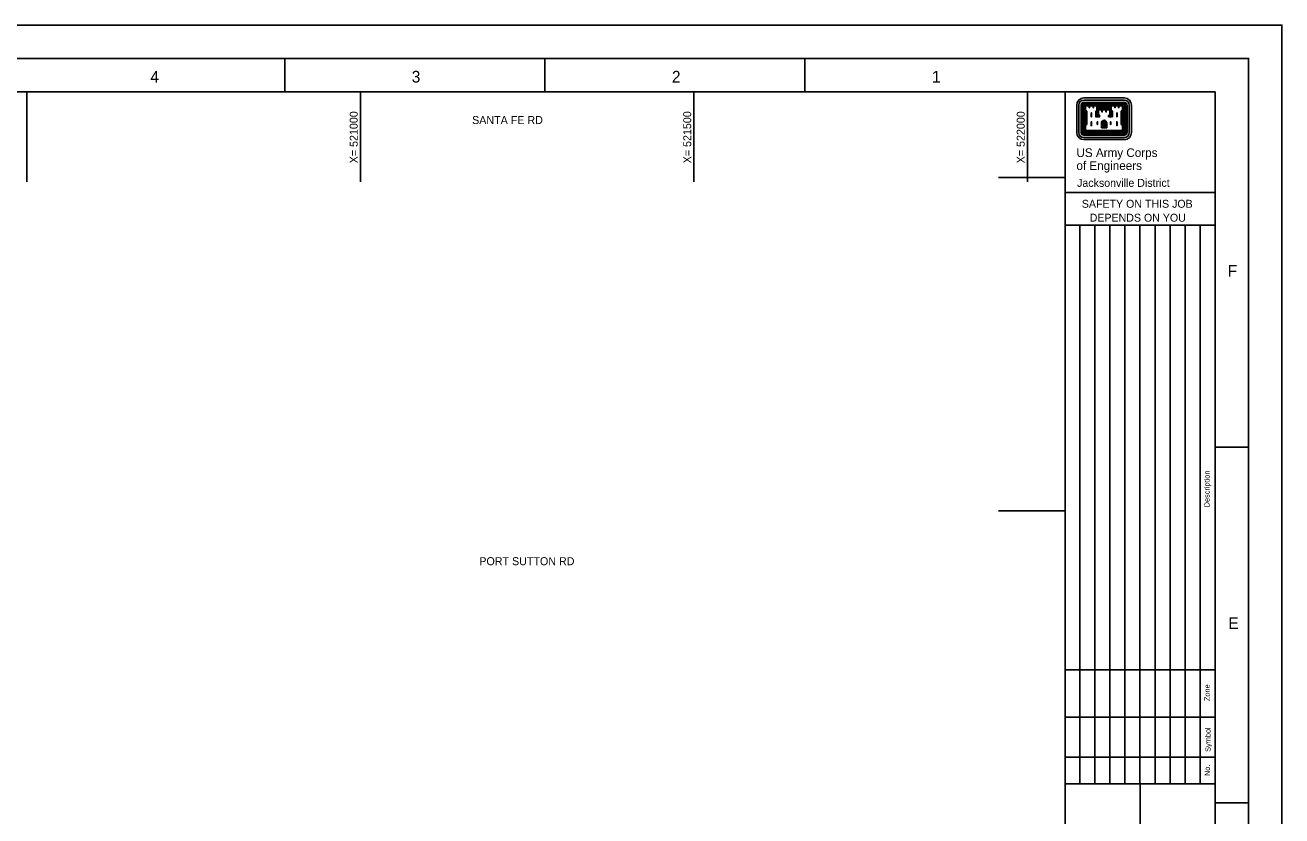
# Model space of a CAD drawing. Extents: x 517982 to 522382, y 1296329 to 1299729.
# Drawn here: x 520497 to 522381, y 1298542 to 1299729 of the extents above; entities that cross this region are included whole.
import ezdxf

# ---------------------------------------------------------------- set-up
doc = ezdxf.new("R2010")
doc.units = 0
for name, color, linetype in [('G-ANNO-NPLT', 7, 'Continuous'), ('G-ANNO-TEXT-LOGO', 7, 'Continuous'), ('G-ANNO-TEXT-TTLB', 7, 'Continuous'), ('G-ANNO-TTLB', 7, 'Continuous'), ('V-ROAD-IDEN', 7, 'Continuous'), ('V-TOPO-COOR-STAT', 7, 'Continuous')]:
    doc.layers.add(name, color=color, linetype=linetype)

msp = doc.modelspace()

# ---------------------------------------------------------------- linework, layer by layer
at = {"layer": 'G-ANNO-NPLT'}
msp.add_lwpolyline([(517981.5, 1299728.6), (522381.5, 1299728.6), (522381.5, 1296328.6), (517981.5, 1296328.6)], close=True, dxfattribs=at)
msp.add_lwpolyline([(522381.5, 1299678.6), (522381.5, 1299728.6), (522331.5, 1299728.6)], dxfattribs=at)
at = {"layer": 'G-ANNO-TEXT-LOGO'}
for p, q in [((522145.4, 1299619.2), (522084.6, 1299619.2)), ((522073.9, 1299608.5), (522073.9, 1299567.5)), ((522077.1, 1299567.5), (522077.1, 1299608.5)), ((522080.6, 1299608.5), (522080.6, 1299567.5)), ((522081.5, 1299608.5), (522081.5, 1299567.5)), ((522082.3, 1299608.5), (522082.3, 1299567.5)), ((522083.2, 1299608.5), (522083.2, 1299567.5)), ((522084.1, 1299608.5), (522084.1, 1299567.5)), ((522084.6, 1299616), (522145.4, 1299616)), ((522145.4, 1299612.6), (522084.6, 1299612.6)), ((522145.4, 1299611.7), (522084.6, 1299611.7)), ((522145.4, 1299610.8), (522084.6, 1299610.8)), ((522145.4, 1299610), (522084.6, 1299610)), ((522145.4, 1299609.1), (522084.6, 1299609.1)), ((522085, 1299608.5), (522085, 1299567.8)), ((522085.8, 1299608.5), (522085.8, 1299568.7)), ((522086.5, 1299599.8), (522086.5, 1299578.8)), ((522087.4, 1299598.9), (522087.4, 1299579.8)), ((522105.7, 1299608.3), (522124.3, 1299608.3)), ((522105.7, 1299607.4), (522124.3, 1299607.4)), ((522105.7, 1299606.6), (522124.3, 1299606.6)), ((522105.7, 1299605.7), (522124.3, 1299605.7)), ((522105.7, 1299604.8), (522124.3, 1299604.8)), ((522105.7, 1299604), (522124.3, 1299604)), ((522105.7, 1299603.1), (522124.3, 1299603.1)), ((522142.6, 1299598.9), (522142.6, 1299579.8)), ((522143.5, 1299599.7), (522143.5, 1299578.9)), ((522144.2, 1299608.5), (522144.2, 1299568.7)), ((522145, 1299608.5), (522145, 1299567.8)), ((522145.9, 1299608.5), (522145.9, 1299567.5)), ((522146.8, 1299608.5), (522146.8, 1299567.5)), ((522147.6, 1299608.5), (522147.6, 1299567.5)), ((522148.5, 1299608.5), (522148.5, 1299567.5)), ((522149.4, 1299608.5), (522149.4, 1299567.5)), ((522152.8, 1299608.5), (522152.8, 1299567.5)), ((522156.1, 1299567.5), (522156.1, 1299608.5)), ((522111, 1299574.6), (522111, 1299581.3)), ((522111.8, 1299574.6), (522111.8, 1299581.3)), ((522112.7, 1299574.6), (522112.7, 1299581.3)), ((522113.6, 1299574.6), (522113.6, 1299581.3)), ((522114.4, 1299574.6), (522114.4, 1299581.3)), ((522115.6, 1299574.6), (522115.6, 1299581.3)), ((522116.4, 1299574.6), (522116.4, 1299581.3)), ((522117.3, 1299574.6), (522117.3, 1299581.3)), ((522118.2, 1299574.6), (522118.2, 1299581.3)), ((522119, 1299574.6), (522119, 1299581.3)), ((522145.4, 1299566.9), (522084.6, 1299566.9)), ((522145.4, 1299566.1), (522084.6, 1299566.1)), ((522145.4, 1299565.2), (522084.6, 1299565.2)), ((522145.4, 1299564.3), (522084.6, 1299564.3)), ((522145.4, 1299563.5), (522084.6, 1299563.5)), ((522145, 1299567.8), (522085, 1299567.8)), ((522144.2, 1299568.7), (522085.8, 1299568.7)), ((522111, 1299574.6), (522119, 1299574.6)), ((522145.4, 1299560), (522084.6, 1299560)), ((522084.6, 1299556.7), (522145.4, 1299556.7))]:
    msp.add_line(p, q, dxfattribs=at)
for points in [[(522086.5, 1299608.5), (522086.5, 1299600.6), (522088.2, 1299598.9), (522088.2, 1299579.8), (522086.5, 1299578), (522086.5, 1299569.3), (522143.5, 1299569.3), (522143.5, 1299578), (522141.7, 1299579.8), (522141.7, 1299598.9), (522143.5, 1299600.6), (522143.5, 1299608.5), (522136, 1299608.5), (522130.2, 1299608.5), (522124.8, 1299608.5), (522124.8, 1299600.6), (522126.7, 1299598.9), (522126.7, 1299591.9), (522122.5, 1299591.9), (522122.5, 1299592.6), (522124.3, 1299594.4), (522124.3, 1299602.2), (522116.8, 1299602.2), (522111, 1299602.2), (522105.7, 1299602.2), (522105.7, 1299594.4), (522107.5, 1299592.6), (522107.5, 1299591.9), (522103.3, 1299591.9), (522103.3, 1299598.9), (522105.1, 1299600.6), (522105.1, 1299608.5), (522097.6, 1299608.5), (522091.8, 1299608.5), (522086.5, 1299608.5)], [(522087.3, 1299607.6), (522087.3, 1299601), (522089.1, 1299599.2), (522089.1, 1299579.4), (522087.3, 1299577.6), (522087.3, 1299570.2), (522142.7, 1299570.2), (522142.7, 1299577.6), (522140.8, 1299579.4), (522140.8, 1299599.2), (522142.7, 1299601), (522142.7, 1299607.6), (522137.3, 1299607.6), (522137.3, 1299604.5), (522136.8, 1299604.5), (522136.8, 1299607.6), (522131.5, 1299607.6), (522131.5, 1299604.5), (522131.1, 1299604.5), (522131.1, 1299607.6), (522125.7, 1299607.6), (522125.7, 1299601), (522127.5, 1299599.2), (522127.5, 1299591.1), (522121.7, 1299591.1), (522121.7, 1299593), (522123.5, 1299594.8), (522123.5, 1299601.4), (522118.1, 1299601.4), (522118.1, 1299598.3), (522117.7, 1299598.3), (522117.7, 1299601.4), (522112.3, 1299601.4), (522112.3, 1299598.3), (522111.8, 1299598.3), (522111.8, 1299601.4), (522106.5, 1299601.4), (522106.5, 1299594.8), (522108.3, 1299593), (522108.3, 1299591.1), (522102.5, 1299591.1), (522102.5, 1299599.2), (522104.3, 1299601), (522104.3, 1299607.6), (522099, 1299607.6), (522099, 1299604.5), (522098.5, 1299604.5), (522098.5, 1299607.6), (522093.1, 1299607.6), (522093.1, 1299604.5), (522092.7, 1299604.5), (522092.7, 1299607.6), (522087.3, 1299607.6)], [(522104.7, 1299599), (522104.2, 1299598.5), (522104.2, 1299592.8), (522106.1, 1299592.8), (522104.8, 1299594.1), (522104.8, 1299599.1)], [(522125.3, 1299599), (522125.8, 1299598.5), (522125.8, 1299592.8), (522124, 1299592.8), (522125.2, 1299594.1), (522125.2, 1299599.1)], [(522095.5, 1299596.9), (522095.5, 1299591.1), (522096.1, 1299591.1), (522096.1, 1299596.9), (522095.5, 1299596.9)], [(522095.5, 1299583.6), (522095.5, 1299577.7), (522096.1, 1299577.7), (522096.1, 1299583.6), (522095.5, 1299583.6)], [(522104.7, 1299583.6), (522104.7, 1299579.5), (522105.2, 1299579.5), (522105.2, 1299583.6), (522104.7, 1299583.6)], [(522125.3, 1299583.6), (522125.3, 1299579.5), (522124.8, 1299579.5), (522124.8, 1299583.6), (522125.3, 1299583.6)], [(522134.4, 1299596.9), (522134.4, 1299591.1), (522133.9, 1299591.1), (522133.9, 1299596.9), (522134.4, 1299596.9)], [(522134.4, 1299583.6), (522134.4, 1299577.7), (522133.9, 1299577.7), (522133.9, 1299583.6), (522134.4, 1299583.6)]]:
    msp.add_lwpolyline(points, dxfattribs=at)
for centre, major_axis, start_param, end_param in [((522084.6, 1299608.5), (10.7, 0), 1.57078, 3.141576), ((522145.3, 1299608.5), (10.7, 0), 6.283169, 7.853965), ((522084.6, 1299608.5), (7.49, 0), 1.57078, 3.141576), ((522084.6, 1299608.5), (4.02, 0), 1.57078, 3.141576), ((522084.6, 1299608.5), (3.15, 0), 1.57078, 3.141576), ((522084.6, 1299608.5), (2.28, 0), 1.57078, 3.141576), ((522084.6, 1299608.5), (1.41, 0), 1.57078, 3.141576), ((522084.6, 1299608.5), (0.546, 0), 1.57078, 3.141576), ((522145.3, 1299608.5), (7.49, 0), 6.28317, 7.853966), ((522145.3, 1299608.5), (4.02, 0), 6.283169, 7.853965), ((522145.3, 1299608.5), (3.15, 0), 6.283169, 7.853965), ((522145.3, 1299608.5), (2.28, 0), 6.283169, 7.853965), ((522145.3, 1299608.5), (1.41, 0), 6.283169, 7.853965), ((522145.3, 1299608.5), (0.546, 0), 6.283169, 7.853965), ((522116.4, 1299580.8), (-5.55, 0), 4.985832, 6.214359), ((522116.4, 1299580.8), (-4.69, 0), 4.947465, 6.21436), ((522116.4, 1299580.8), (-3.82, 0), 4.947465, 6.21436), ((522116.4, 1299580.8), (-2.95, 0), 4.947465, 6.21436), ((522113.4, 1299580.8), (2.08, 0), 0.068794, 1.335689), ((522113.4, 1299580.8), (2.95, 0), 0.068794, 1.335689), ((522113.4, 1299580.8), (3.82, 0), 0.068795, 1.335689), ((522116.4, 1299580.8), (-2.08, 0), 4.947465, 6.214359), ((522113.4, 1299580.8), (4.69, 0), 0.068795, 1.335689), ((522113.4, 1299580.8), (5.55, 0), 0.068795, 1.29842), ((522084.6, 1299567.4), (-10.7, 0), 6.28317, 7.853966), ((522084.6, 1299567.4), (-7.49, 0), 6.28317, 7.853966), ((522084.6, 1299567.4), (-4.02, 0), 6.28317, 7.853966), ((522084.6, 1299567.4), (-3.15, 0), 6.28317, 7.853966), ((522084.6, 1299567.4), (-2.28, 0), 6.28317, 7.853966), ((522084.6, 1299567.4), (-1.41, 0), 6.28317, 7.853966), ((522084.6, 1299567.4), (-0.546, 0), 6.28317, 7.853966), ((522145.3, 1299567.4), (4.02, 0), 4.712373, 6.28317), ((522145.3, 1299567.4), (3.15, 0), 4.712373, 6.28317), ((522145.3, 1299567.4), (2.28, 0), 4.712373, 6.28317), ((522145.3, 1299567.4), (1.41, 0), 4.712373, 6.28317), ((522145.3, 1299567.4), (0.546, 0), 4.712373, 6.28317), ((522145.3, 1299567.4), (10.7, 0), 4.712373, 6.28317), ((522145.3, 1299567.4), (-7.49, 0), 1.570781, 3.141577)]:
    msp.add_ellipse(centre, major_axis=major_axis, ratio=0.99964, start_param=start_param, end_param=end_param, dxfattribs=at)
at = {"layer": 'G-ANNO-TTLB'}
for p, q in [((520886.5, 1299678.6), (520886.5, 1299628.6)), ((521276.5, 1299678.6), (521276.5, 1299628.6)), ((521666.5, 1299678.6), (521666.5, 1299628.6)), ((522056.5, 1299628.6), (522056.5, 1296428.6)), ((522056.5, 1299477.3), (522281.5, 1299477.3)), ((522055.9, 1299428.2), (522280.9, 1299428.2)), ((522078.8, 1299428.2), (522078.8, 1298590.3)), ((522101.3, 1299428.2), (522101.3, 1298590.3)), ((522123.8, 1299428.2), (522123.8, 1298590.3)), ((522146.3, 1299428.2), (522146.3, 1298590.3)), ((522168.8, 1299428.2), (522168.8, 1298590.3)), ((522191.3, 1299428.2), (522191.3, 1298590.3)), ((522213.8, 1299428.2), (522213.8, 1298590.3)), ((522236.3, 1299428.2), (522236.3, 1298590.3)), ((522258.8, 1299428.2), (522258.8, 1298590.3)), ((522331.5, 1299095.1), (522281.5, 1299095.1)), ((522056.5, 1298761.3), (522281.5, 1298761.3)), ((522056.5, 1298690.1), (522281.5, 1298690.1)), ((522056.5, 1298630.1), (522281.5, 1298630.1)), ((522056.5, 1298590.3), (522281.5, 1298590.3)), ((522168.3, 1297730.7), (522169, 1298590.3)), ((522169, 1298590.3), (522169, 1298554.9)), ((522331.5, 1298561.8), (522281.5, 1298561.8))]:
    msp.add_line(p, q, dxfattribs=at)
for points in [[(518031.5, 1296378.6), (522331.5, 1296378.6), (522331.5, 1299678.6), (518031.5, 1299678.6)], [(522281.5, 1299628.6), (518156.5, 1299628.6), (518156.5, 1296428.6), (522281.5, 1296428.6)]]:
    msp.add_lwpolyline(points, close=True, dxfattribs=at)
at = {"layer": 'V-TOPO-COOR-STAT'}
for p, q in [((520500, 1299493.6), (520500, 1299628.6)), ((521000, 1299493.6), (521000, 1299628.6)), ((521500, 1299493.6), (521500, 1299628.6)), ((522000, 1299493.6), (522000, 1299628.6)), ((522056.5, 1299500), (521956.5, 1299500)), ((522056.5, 1299000), (521956.5, 1299000))]:
    msp.add_line(p, q, dxfattribs=at)

# ---------------------------------------------------------------- texts
at = {"layer": 'G-ANNO-TEXT-TTLB'}
for s, height, p in [('US Army Corps', 13.086, (522073.5, 1299530.6)), ('of Engineers', 13.086, (522073.5, 1299511.2)), ('Jacksonville District', 11.9, (522074.5, 1299485.9)), ('SAFETY ON THIS JOB', 11.9, (522081.6, 1299454.5)), ('DEPENDS ON YOU', 11.9, (522093.4, 1299433.6))]:
    msp.add_text(s, height=height, dxfattribs=at).set_placement(p)
for s, p in [('Description', (522273.1, 1299005)), ('Zone', (522273.4, 1298714.3)), ('Symbol', (522274.6, 1298638)), ('No.', (522273.6, 1298601.9))]:
    msp.add_text(s, height=8, rotation=90, dxfattribs=at).set_placement(p)
at = {"layer": 'G-ANNO-TTLB'}
for s, p in [('4', (520685.2, 1299642.4)), ('3', (521076.9, 1299642.4)), ('2', (521467, 1299642.4)), ('1', (521856.9, 1299642.4)), ('F', (522300.3, 1299351.2)), ('E', (522301.1, 1298822.4))]:
    msp.add_text(s, height=17.5, dxfattribs=at).set_placement(p)
at = {"layer": 'V-ROAD-IDEN'}
for s, p in [('SANTA FE RD', (521167.5, 1299580.1)), ('PORT SUTTON RD', (521178.3, 1298918.2))]:
    msp.add_text(s, height=12, dxfattribs=at).set_placement(p)
at = {"layer": 'V-TOPO-COOR-STAT'}
for s, p in [('X= 521000', (520996, 1299521.2)), ('X= 521500', (521496, 1299521.2)), ('X= 522000', (521996, 1299521.2))]:
    msp.add_text(s, height=12, rotation=90, dxfattribs=at).set_placement(p)

doc.saveas('drawing.dxf')
